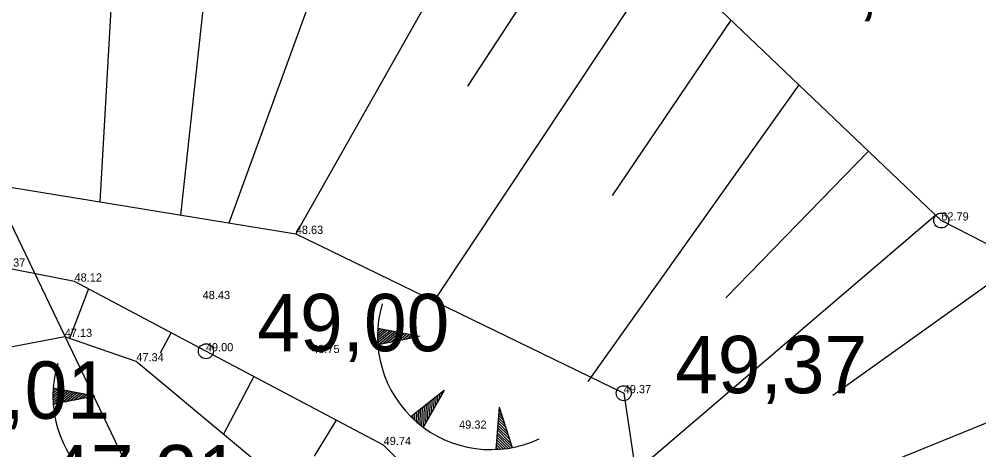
# Model space of a CAD drawing. Extents: x 700746 to 706058, y 6570320 to 6580460.
# Drawn here: x 703072.2 to 703113.2, y 6577401.06 to 6577419.46 of the extents above; entities that cross this region are included whole.
import ezdxf

# ---------------------------------------------------------------- set-up
doc = ezdxf.new("R2010")
doc.units = 0
for name, color, linetype in [('KORGUS-EH2000', 7, 'Continuous'), ('Lõige', 7, 'Continuous'), ('MOOTKORG-EH2000', 7, 'Continuous'), ('RELJEEF', 7, 'Continuous'), ('vahekiht', 7, 'Continuous')]:
    doc.layers.add(name, color=color, linetype=linetype)

msp = doc.modelspace()

# ---------------------------------------------------------------- linework, layer by layer
at = {"layer": 'KORGUS-EH2000'}
for centre in [(703111.597, 6577410.861), (703080.179, 6577405.273), (703098.028, 6577403.48)]:
    msp.add_circle(centre, 0.32, dxfattribs=at)
at = {"layer": 'Lõige'}
msp.add_lwpolyline([(703070.672, 6577165.983), (703074.081, 6577220.567), (703082.822, 6577285.406), (703068.681, 6577320.797), (703082.772, 6577387.952), (703057.768, 6577440.12), (703054.894, 6577468.198)], dxfattribs=at)
at = {"layer": 'RELJEEF'}
for p, q in [((703076.947, 6577434.697), (703075.65, 6577411.654)), ((703081.591, 6577433.914), (703079.094, 6577411.091)), ((703089.303, 6577433.071), (703081.162, 6577410.753)), ((703093.752, 6577427.503), (703084.018, 6577410.287)), ((703091.371, 6577416.595), (703096.711, 6577424.811)), ((703099.669, 6577422.119), (703089.992, 6577407.524)), ((703097.546, 6577411.928), (703102.618, 6577419.417)), ((703105.514, 6577416.657), (703096.495, 6577403.975)), ((703102.39, 6577407.559), (703108.49, 6577413.821)), ((703111.366, 6577411.082), (703098.523, 6577400.121)), ((703106.969, 6577403.389), (703114.976, 6577409.13)), ((703075.159, 6577407.936), (703074.349, 6577405.814)), ((703087.515, 6577406.143), (703087.622, 6577406.228)), ((703089.302, 6577405.903), (703087.521, 6577406.247)), ((703078.241, 6577405.209), (703078.693, 6577406.062)), ((703087.51, 6577405.933), (703087.828, 6577406.188)), ((703087.51, 6577405.831), (703087.931, 6577406.168)), ((703087.511, 6577406.037), (703087.725, 6577406.208)), ((703087.513, 6577405.731), (703088.034, 6577406.148)), ((703087.518, 6577405.632), (703088.137, 6577406.128)), ((703089.302, 6577405.903), (703087.523, 6577405.554)), ((703087.556, 6577405.56), (703088.24, 6577406.108)), ((703087.725, 6577405.594), (703088.344, 6577406.088)), ((703087.895, 6577405.627), (703088.447, 6577406.068)), ((703088.065, 6577405.66), (703088.55, 6577406.048)), ((703088.234, 6577405.693), (703088.653, 6577406.029)), ((703088.404, 6577405.727), (703088.756, 6577406.009)), ((703088.574, 6577405.76), (703088.859, 6577405.989)), ((703088.743, 6577405.793), (703088.962, 6577405.969)), ((703088.913, 6577405.827), (703089.065, 6577405.949)), ((703089.082, 6577405.86), (703089.169, 6577405.929)), ((703121.467, 6577405.451), (703099.093, 6577396.33)), ((703082.228, 6577404.191), (703080.929, 6577401.732)), ((703073.647, 6577403.387), (703073.965, 6577403.642)), ((703073.648, 6577403.285), (703074.069, 6577403.622)), ((703073.649, 6577403.491), (703073.862, 6577403.662)), ((703073.651, 6577403.185), (703074.172, 6577403.602)), ((703073.653, 6577403.597), (703073.759, 6577403.682)), ((703073.655, 6577403.086), (703074.275, 6577403.582)), ((703075.44, 6577403.357), (703073.659, 6577403.701)), ((703075.44, 6577403.357), (703073.66, 6577403.008)), ((703073.693, 6577403.014), (703074.378, 6577403.562)), ((703073.863, 6577403.048), (703074.481, 6577403.543)), ((703074.033, 6577403.081), (703074.584, 6577403.523)), ((703074.202, 6577403.114), (703074.687, 6577403.503)), ((703074.372, 6577403.148), (703074.791, 6577403.483)), ((703074.542, 6577403.181), (703074.894, 6577403.463)), ((703074.711, 6577403.214), (703074.997, 6577403.443)), ((703074.881, 6577403.248), (703075.1, 6577403.423)), ((703075.05, 6577403.281), (703075.203, 6577403.403)), ((703075.22, 6577403.314), (703075.306, 6577403.383)), ((703090.364, 6577403.598), (703088.942, 6577402.472)), ((703090.364, 6577403.598), (703089.469, 6577402.021)), ((703090.083, 6577403.103), (703090.093, 6577403.383)), ((703090.169, 6577403.253), (703090.175, 6577403.449)), ((703090.254, 6577403.404), (703090.258, 6577403.514)), ((703089.571, 6577402.201), (703089.599, 6577402.992)), ((703089.657, 6577402.351), (703089.681, 6577403.057)), ((703089.742, 6577402.502), (703089.764, 6577403.123)), ((703089.827, 6577402.652), (703089.846, 6577403.188)), ((703089.913, 6577402.802), (703089.928, 6577403.253)), ((703089.998, 6577402.953), (703090.011, 6577403.318)), ((703089.018, 6577402.399), (703089.023, 6577402.536)), ((703089.095, 6577402.328), (703089.105, 6577402.601)), ((703089.173, 6577402.259), (703089.187, 6577402.666)), ((703089.251, 6577402.193), (703089.27, 6577402.731)), ((703089.329, 6577402.129), (703089.352, 6577402.797)), ((703089.406, 6577402.069), (703089.434, 6577402.862)), ((703089.486, 6577402.051), (703089.517, 6577402.927)), ((703092.708, 6577402.882), (703092.572, 6577401.073)), ((703092.881, 6577402.339), (703092.682, 6577402.536)), ((703092.829, 6577402.504), (703092.69, 6577402.641)), ((703092.776, 6577402.668), (703092.697, 6577402.746)), ((703092.708, 6577402.882), (703093.261, 6577401.155)), ((703084.824, 6577400.794), (703085.766, 6577402.324)), ((703093.04, 6577401.845), (703092.658, 6577402.222)), ((703092.987, 6577402.01), (703092.666, 6577402.327)), ((703092.934, 6577402.174), (703092.674, 6577402.432)), ((703093.25, 6577401.187), (703092.627, 6577401.803)), ((703093.198, 6577401.351), (703092.635, 6577401.908)), ((703093.145, 6577401.516), (703092.643, 6577402.013)), ((703093.092, 6577401.68), (703092.65, 6577402.117)), ((703092.885, 6577401.098), (703092.595, 6577401.384)), ((703092.986, 6577401.11), (703092.603, 6577401.489)), ((703093.086, 6577401.124), (703092.611, 6577401.594)), ((703093.183, 6577401.14), (703092.619, 6577401.698)), ((703092.677, 6577401.079), (703092.58, 6577401.175)), ((703092.782, 6577401.087), (703092.588, 6577401.279))]:
    msp.add_line(p, q, dxfattribs=at)
for points in [[(703118.359, 6577407.397), (703111.597, 6577410.861), (703102.182, 6577419.832), (703093.601, 6577427.641), (703091.475, 6577432.833), (703081.591, 6577433.914)], [(703032.907, 6577408.421), (703037.765, 6577411.102), (703040.668, 6577412.287), (703054.691, 6577412.073), (703060.912, 6577414.062), (703084.018, 6577410.287), (703098.028, 6577403.48), (703100.237, 6577388.654)], [(703100.237, 6577388.654), (703087.773, 6577401.264), (703080.179, 6577405.273), (703074.568, 6577408.25), (703071.295, 6577408.889), (703067.368, 6577408.724), (703064.976, 6577405.731), (703053.453, 6577408.44), (703041.693, 6577411.015), (703037.631, 6577409.489)], [(703093.711, 6577390.508), (703084.839, 6577398.464), (703077.208, 6577404.841), (703074.15, 6577405.882), (703069.505, 6577405.003), (703065.683, 6577402.388), (703057.567, 6577402.61), (703052.524, 6577404.378), (703038.351, 6577405.195), (703032.818, 6577408.582), (703026.771, 6577405.259)]]:
    msp.add_lwpolyline(points, dxfattribs=at)
for centre in [(703092.353, 6577405.911), (703078.491, 6577403.366)]:
    msp.add_arc(centre, 4.844, 163.4234, 295.1745, dxfattribs=at)
at = {"layer": 'vahekiht'}
msp.add_open_spline([(702979.832, 6577405.847), (702968.107, 6577383.619), (702956.937, 6577340.299), (703007.686, 6577297.989), (703005.438, 6577248.778), (703018.696, 6577224.523), (703025.875, 6577210.26), (703039.06, 6577207.602), (703055.215, 6577200.514), (703065.918, 6577180.529), (703097.43, 6577186.962), (703125.436, 6577225.369), (703148.077, 6577281.443), (703138.931, 6577341.457), (703139.445, 6577382.673), (703130.544, 6577416.204), (703100.319, 6577426.617), (703061.125, 6577412.698), (703017.391, 6577461.228), (702989.678, 6577424.511), (702979.832, 6577405.847)], degree=3, dxfattribs=at)
msp.add_open_spline([(702979.832, 6577405.847), (702968.107, 6577383.619), (702956.937, 6577340.299), (703007.686, 6577297.989), (703005.438, 6577248.778), (703018.696, 6577224.523), (703025.875, 6577210.26), (703039.06, 6577207.602), (703055.215, 6577200.514), (703065.918, 6577180.529), (703097.43, 6577186.962), (703125.436, 6577225.369), (703148.077, 6577281.443), (703138.931, 6577341.457), (703139.445, 6577382.673), (703130.544, 6577416.204), (703100.319, 6577426.617), (703061.125, 6577412.698), (703017.391, 6577461.228), (702989.678, 6577424.511), (702979.832, 6577405.847)], degree=3, dxfattribs=at)

# ---------------------------------------------------------------- texts
at = {"layer": 'KORGUS-EH2000'}
for s, p in [('62,43', (703104.382, 6577419.832)), ('49,00', (703082.379, 6577405.273)), ('49,37', (703100.228, 6577403.48)), ('47,01', (703067.883, 6577402.388)), ('47,21', (703073.445, 6577398.816))]:
    msp.add_text(s, height=2.45, dxfattribs=at).set_placement(p)
at = {"layer": 'MOOTKORG-EH2000'}
for s, p in [('62.79', (703111.597, 6577410.861)), ('48.63', (703084.018, 6577410.287)), ('49.37', (703071.295, 6577408.889)), ('48.12', (703074.568, 6577408.25)), ('48.43', (703080.042, 6577407.501)), ('47.13', (703074.15, 6577405.882)), ('49.00', (703080.179, 6577405.273)), ('48.75', (703084.719, 6577405.196)), ('47.34', (703077.208, 6577404.841)), ('47.34', (703077.208, 6577404.841)), ('49.37', (703098.028, 6577403.48)), ('49.32', (703090.998, 6577401.962)), ('49.74', (703087.773, 6577401.264))]:
    msp.add_text(s, height=0.35, dxfattribs=at).set_placement(p)

doc.saveas('drawing.dxf')
